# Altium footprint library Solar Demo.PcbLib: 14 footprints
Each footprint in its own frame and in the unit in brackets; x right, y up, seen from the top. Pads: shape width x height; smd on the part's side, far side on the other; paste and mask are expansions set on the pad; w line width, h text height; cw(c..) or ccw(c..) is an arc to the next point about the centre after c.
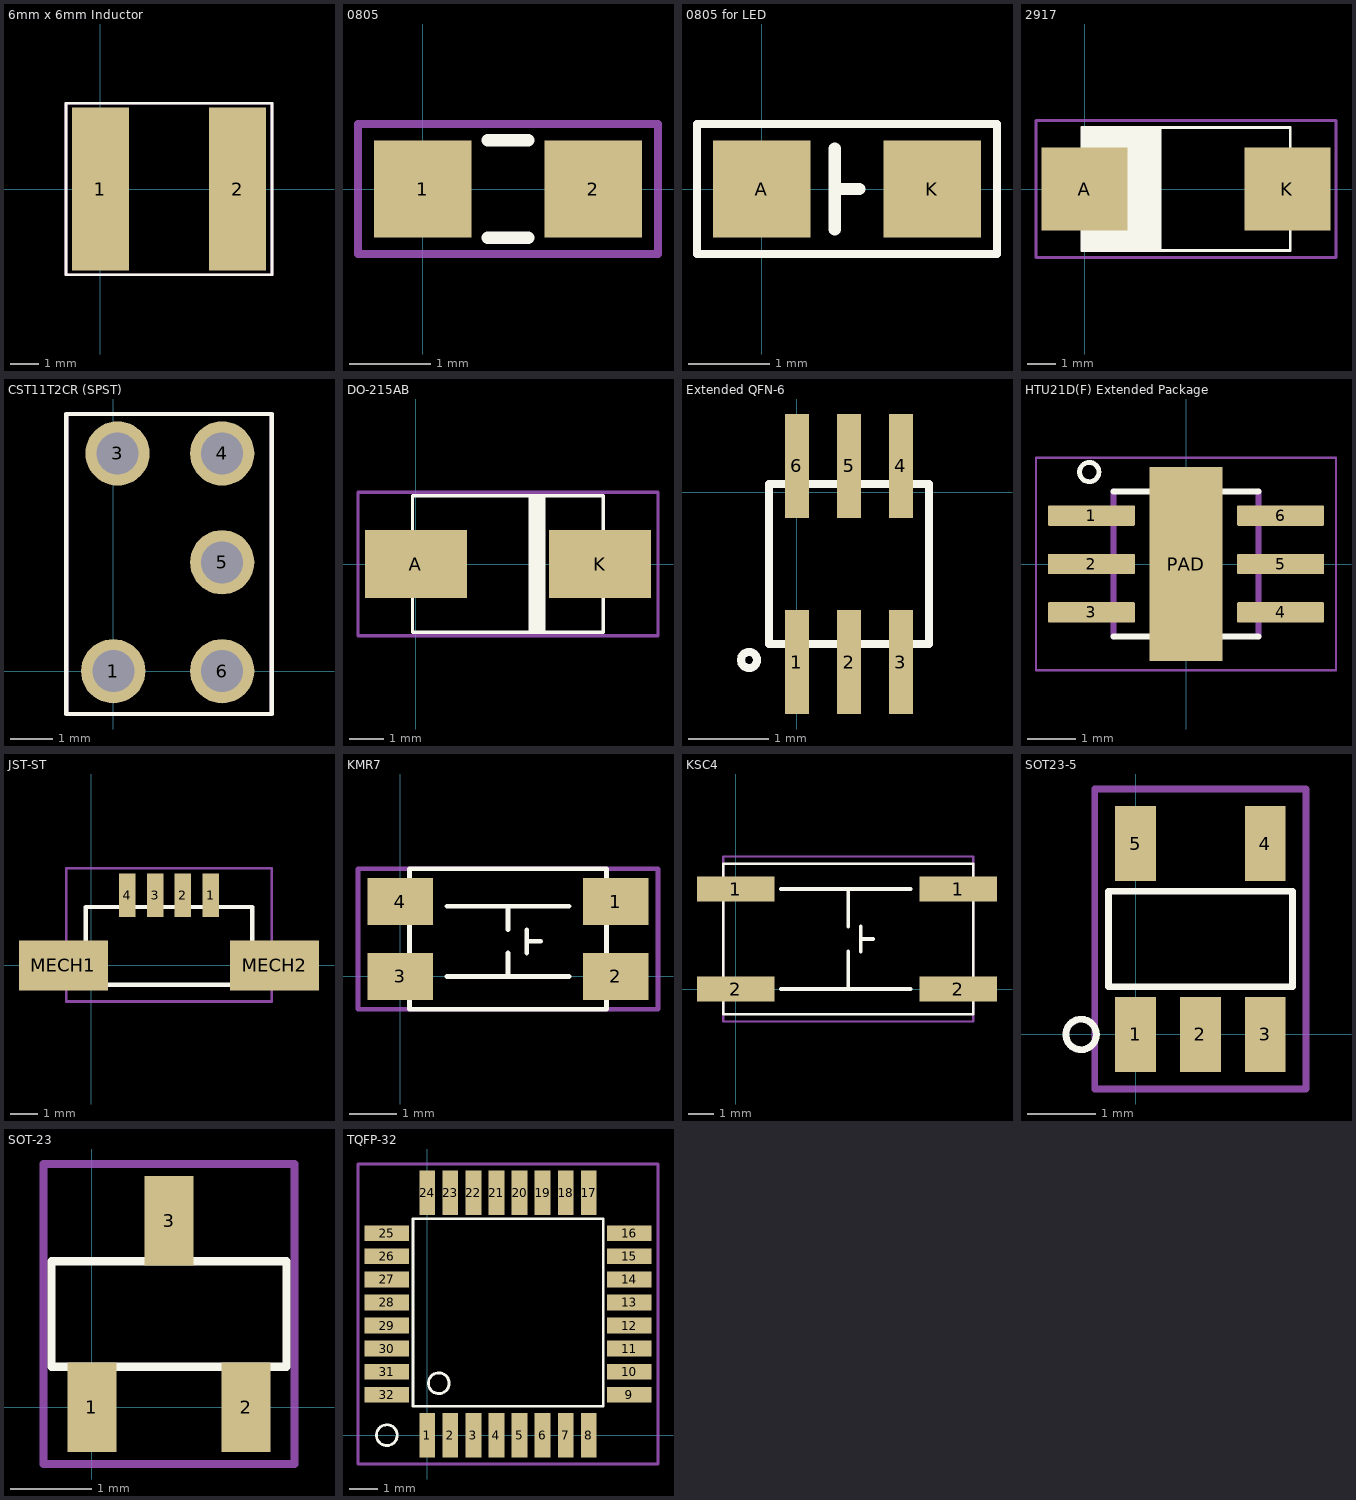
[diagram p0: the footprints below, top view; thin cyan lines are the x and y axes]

## 6mm x 6mm Inductor [mm] "For ASPI-6045S-331M-T"
pads (2):
  rect 2x5.7 smd: 1(0,0) 2(4.8,0)
Top Overlay:
  lines w0.1: -1.2,-3 6,-3 6,3 -1.2,3 -1.2,-3
Top Assembly:
  lines w0.1: -1.2,-3 6,-3 6,3 -1.2,3 -1.2,-3

## 0805 [mm] "Non-Polarized"
pads (2):
  rect 1.2x1.2 smd: 1(0,0) 2(2.1,0)
Top Overlay:
  lines w0.152: 0.8,-0.6 1.3,-0.6 ; 0.8,0.6 1.3,0.6
Top Courtyard:
  lines w0.1: -0.8,-0.8 -0.8,0.8 2.9,0.8 2.9,-0.8 -0.8,-0.8

## 0805 for LED [mm] "Polarized 0805 Package"
pads (2):
  rect 1.2x1.2 smd: A(0,0) K(2.1,0)
Top Overlay:
  lines w0.1: -0.8,-0.8 2.9,-0.8 2.9,0.8 -0.8,0.8 -0.8,-0.8
  lines w0.152: 0.9,0.5 0.9,-0.5 0.9,0 1.2,0
Top Courtyard:
  lines w0.1: -0.8,-0.8 2.9,-0.8 2.9,0.8 -0.8,0.8 -0.8,-0.8

## 2917 [mm] "2917 SMD Package"
pads (2):
  rect 3x2.9 smd: A(0,0) K(7.1,0)
Top Overlay:
  rectangle: -0.1,-2.1 2.7,2.15
  lines w0.1: -0.1,-2.15 7.2,-2.15 7.2,2.15 -0.1,2.15 -0.1,-2.15
Top Courtyard:
  lines w0.1: -1.7,-2.4 8.8,-2.4 8.8,2.4 -1.7,2.4 -1.7,-2.4

## CST11T2CR (SPST) [mm] "SPST Switch Footprint for CST11T2CR"
pads (5):
  round 1.5 hole 0.98: 1(0,0) 3(0.1,5.08) 4(2.54,5.08) 5(2.54,2.54) 6(2.54,0)
Top Overlay:
  lines w0.1: -1.1,-1 3.7,-1 3.7,6 -1.1,6 -1.1,-1
Top Courtyard:
  lines w0.1: -1.1,-1 3.7,-1 3.7,6 -1.1,6 -1.1,-1

## DO-215AB [mm]
pads (2):
  rect 3x2 smd: A(0,0) K(5.4,0)
Top Overlay:
  rectangle: 3.3,-2 3.8,2
  lines w0.1: -0.1,-2 5.5,-2 5.5,2 -0.1,2 -0.1,-2
Top Courtyard:
  lines w0.1: -1.7,-2.1 7.1,-2.1 7.1,2.1 -1.7,2.1 -1.7,-2.1

## Extended QFN-6 [mm]
pads (6):
  rect 0.3x1.3 smd: 1(0,-2.125) 2(0.65,-2.125) 3(1.3,-2.125) 4(1.3,0.325) 5(0.65,0.325) 6(0,0.325)
Top Overlay:
  circle w0.1: c-0.6,-2.1 r0.1
  lines w0.1: -0.35,-1.9 1.65,-1.9 1.65,0.1 -0.35,0.1 -0.35,-1.9
Top Courtyard:
  lines w0.1: -0.35,-1.9 1.65,-1.9 1.65,0.1 -0.35,0.1 -0.35,-1.9

## HTU21D(F) Extended Package [mm] "HTU21D(F) Humidity Sensor with Extended Pads"
pads (7):
  rrect11% 1.8x0.42 smd: 1(-1.955,1) 2(-1.955,0) 3(-1.955,-1) 4(1.955,-1) 5(1.955,0) 6(1.955,1)
  rect 1.5x4 smd paste-2: PAD(0,0)
Top Overlay:
  circle w0.1: c-2,1.9 r0.2
  lines w0.127: -1.5,-1.5 1.5,-1.5 ; -1.5,1.5 1.5,1.5
Top Paste:
  region: 0.47,-0.75 -0.47,-0.75 -0.47,0.75 0.47,0.75
Top 3D Body:
  lines w0.127: -1.5,-1.5 -1.5,1.5 ; 1.5,-1.5 1.5,1.5
Top Courtyard:
  lines w0.05: -3.1,-2.2 -3.1,2.2 3.1,2.2 3.1,-2.2 -3.1,-2.2
3D body "step_temp.STEP": height 1, standoff 0, extent -1.5,-1.5 1.5,1.5

## JST-ST [mm] "Stemma QT Connector"
pads (6):
  rect 0.6x1.55 smd: 1(4.3,2.525) 2(3.3,2.525) 3(2.3,2.525) 4(1.3,2.525)
  rect 3.2x1.8 smd: MECH1(-1,0) MECH2(6.6,0)
Top Overlay:
  lines w0.152: -0.2,-0.7 5.8,-0.7 5.8,2.1 -0.2,2.1 -0.2,-0.7
Top Courtyard:
  lines w0.1: -0.9,-1.3 6.5,-1.3 6.5,3.5 -0.9,3.5 -0.9,-1.3

## KMR7 [mm] "SPST Footprint for KMR7 Series SW"
pads (4):
  rect 1.4x1 smd: 1(4.6,1.6) 2(4.6,0) 3(0,0) 4(0,1.6)
Top Overlay:
  lines w0.1: 1,0 3.6,0 ; 1,1.5 3.6,1.5 ; 2.3,0 2.3,0.5 ; 2.3,1 2.3,1.5 ; 2.7,0.5 2.7,1 ; 2.7,0.75 3,0.75 ; 0.2,-0.7 4.4,-0.7 4.4,2.3 0.2,2.3 0.2,-0.7
Top Courtyard:
  lines w0.1: -0.9,-0.7 5.5,-0.7 5.5,2.3 -0.9,2.3 -0.9,-0.7

## KSC4 [mm] "Layout for KSC4 Series Pushbuttons (Ex: KSC421G 70SH LFS )"
pads (4):
  rect 3.1x1 smd: 1(0,4) 1(8.9,4) 2(0,0) 2(8.9,0)
Top Overlay:
  lines w0.1: -0.5,-1 9.5,-1 9.5,5 -0.5,5 -0.5,-1
  lines w0.152: 1.8,0 7,0 ; 1.8,4 7,4 ; 4.5,0 4.5,1.5 ; 4.5,2.5 4.5,4 ; 5,1.5 5,2.5 ; 5,2 5.5,2
Top Courtyard:
  lines w0.1: -0.5,-1.3 9.5,-1.3 9.5,5.3 -0.5,5.3 -0.5,-1.3

## SOT23-5 [mm]
pads (5):
  rect 0.6x1.1 smd: 1(0,0) 2(0.95,0) 3(1.9,0) 4(1.9,2.8) 5(0,2.8)
Top Overlay:
  circle w0.1: c-0.8,0 r0.224
  lines w0.1: -0.4,0.7 2.3,0.7 2.3,2.1 -0.4,2.1 -0.4,0.7
Top Courtyard:
  lines w0.1: -0.6,-0.8 2.5,-0.8 2.5,3.6 -0.6,3.6 -0.6,-0.8

## SOT-23 [mm]
pads (3):
  rect 0.6x1.1 smd: 1(0,0) 2(1.9,0) 3(0.95,2.3)
Top Overlay:
  lines w0.1: -0.5,0.5 2.4,0.5 2.4,1.8 -0.5,1.8 -0.5,0.5
Top Courtyard:
  lines w0.1: -0.6,-0.7 2.5,-0.7 2.5,3 -0.6,3 -0.6,-0.7

## TQFP-32 [mm]
pads (32):
  rect 0.55x1.55 smd: 1(0,0) 2(0.8,0) 3(1.6,0) 4(2.4,0) 5(3.2,0) 6(4,0) 7(4.8,0) 8(5.6,0) 17(5.6,8.4) 18(4.8,8.4) 19(4,8.4) 20(3.2,8.4) 21(2.4,8.4) 22(1.6,8.4) 23(0.8,8.4) 24(0,8.4)
  rect 1.55x0.55 smd: 9(7,1.4) 10(7,2.2) 11(7,3) 12(7,3.8) 13(7,4.6) 14(7,5.4) 15(7,6.2) 16(7,7) 25(-1.4,7) 26(-1.4,6.2) 27(-1.4,5.4) 28(-1.4,4.6) 29(-1.4,3.8) 30(-1.4,3) 31(-1.4,2.2) 32(-1.4,1.4)
Top Overlay:
  circle w0.1: c0.4,1.8 r0.361
  circle w0.1: c-1.4,0 r0.361
  lines w0.1: -0.5,1 6.1,1 6.1,7.5 -0.5,7.5 -0.5,1
Top Courtyard:
  lines w0.1: -2.4,-1 8,-1 8,9.4 -2.4,9.4 -2.4,-1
